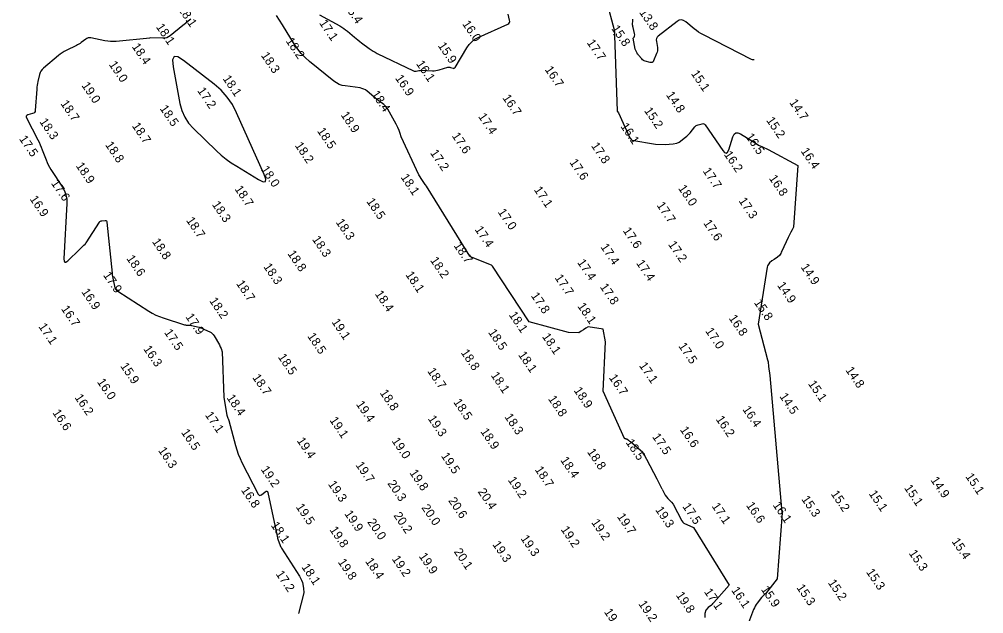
# Model space of a CAD drawing. Extents: x 824616 to 827440, y 158441 to 163197.
# Drawn here: x 826350 to 826901, y 160229 to 160569 of the extents above; entities that cross this region are included whole.
import ezdxf

# ---------------------------------------------------------------- set-up
doc = ezdxf.new("R2010")
doc.units = 0
for name, color, linetype in [('V-CHAN-CONT-EL14', 7, 'Continuous'), ('V-CHAN-CONT-EL16', 7, 'Continuous'), ('V-CHAN-CONT-EL18', 7, 'Continuous'), ('V-TOPO-SOUN', 7, 'Continuous')]:
    doc.layers.add(name, color=color, linetype=linetype)

msp = doc.modelspace()

# ---------------------------------------------------------------- linework, layer by layer
at = {"layer": 'V-CHAN-CONT-EL14'}
msp.add_lwpolyline([(826769.47, 160545.78), (826769.11, 160545.65), (826768.48, 160545.66), (826767.82, 160545.89), (826740.39, 160559.99), (826739.01, 160560.75), (826737.67, 160561.58), (826736.39, 160562.48), (826735.14, 160563.46), (826730.28, 160567.49), (826729.06, 160568.25), (826727.83, 160568.52), (826726.59, 160568.28), (826725.35, 160567.56), (826714.63, 160559.17), (826714.03, 160558.57), (826713.64, 160557.88), (826713.46, 160557.12), (826713.5, 160556.26), (826714.1, 160552.69), (826714.18, 160551.81), (826714.14, 160550.94), (826713.98, 160550.08), (826713.68, 160549.24), (826711.92, 160545.14), (826711.6, 160544.6), (826711.17, 160544.27), (826710.65, 160544.14), (826710.03, 160544.21), (826707.2, 160544.94), (826706.62, 160545.14), (826706.1, 160545.41), (826705.62, 160545.76), (826705.19, 160546.19), (826703.35, 160548.33), (826703.07, 160548.68), (826702.81, 160549.04), (826702.59, 160549.43), (826702.38, 160549.83), (826701.48, 160551.79), (826700.33, 160558.15), (826700.8, 160558.7), (826701.08, 160559.31), (826701.17, 160559.97), (826701.07, 160560.68), (826700.17, 160564.19), (826700.06, 160564.66), (826699.99, 160565.13), (826699.96, 160565.62), (826699.96, 160566.1), (826700.03, 160568.04), (826700.05, 160568.53), (826700.06, 160569.02)], dxfattribs=at)
at = {"layer": 'V-CHAN-CONT-EL16'}
for points in [[(826685.09, 160579.19), (826689.32, 160562.78), (826689.58, 160561.15), (826689.58, 160559.59), (826689.22, 160560.38)], [(826521.11, 160571.49), (826532.72, 160565.08), (826533.85, 160564.42), (826534.94, 160563.7), (826535.99, 160562.93), (826537.01, 160562.11), (826541.01, 160558.72), (826542.02, 160557.88), (826543.04, 160557.05), (826544.07, 160556.24), (826545.11, 160555.44), (826549.44, 160552.18), (826550.52, 160551.4), (826551.65, 160550.68), (826552.81, 160550.02), (826554, 160549.41), (826574.83, 160539.47), (826575.2, 160539.33), (826575.57, 160539.25), (826575.95, 160539.23), (826576.33, 160539.28), (826577.9, 160539.6), (826578.29, 160539.66), (826578.68, 160539.71), (826579.08, 160539.73), (826579.48, 160539.72), (826585.55, 160539.49), (826586.53, 160539.49), (826587.5, 160539.57), (826588.46, 160539.74), (826589.41, 160539.98), (826594.3, 160541.44), (826594.69, 160541.52), (826595.07, 160541.55), (826595.46, 160541.51), (826595.85, 160541.41), (826597.39, 160540.9), (826597.75, 160540.83), (826598.07, 160540.88), (826598.34, 160541.05), (826598.57, 160541.34), (826605.23, 160552.61), (826606.53, 160554.47), (826608.06, 160556.08), (826609.82, 160557.43), (826611.81, 160558.51), (826628.57, 160566.1), (826629.22, 160566.51), (826629.62, 160567.04), (826629.79, 160567.69), (826629.7, 160568.45), (826628.87, 160571.75)], [(826689.58, 160559.59), (826691.18, 160516.44), (826691.83, 160515.44), (826698.23, 160501.57), (826698.34, 160501.36), (826698.46, 160501.15), (826698.6, 160500.96), (826698.75, 160500.77), (826699.38, 160500.04), (826699.49, 160499.86), (826713.05, 160497.62), (826718.59, 160497.32)], [(826718.59, 160497.32), (826723.03, 160497.75), (826725.26, 160498.12), (826726.55, 160498.72), (826730.25, 160501.49), (826730.92, 160502.1), (826731.56, 160502.74), (826732.17, 160503.41), (826732.76, 160504.1), (826735.45, 160507.45), (826735.84, 160507.87), (826736.28, 160508.2), (826736.77, 160508.46), (826737.32, 160508.64), (826739.59, 160509.19), (826740.13, 160509.25), (826740.61, 160509.15), (826741.03, 160508.9), (826741.39, 160508.5), (826751.48, 160493.86), (826752.52, 160492.7), (826753.42, 160492.4), (826754.19, 160492.95), (826754.84, 160494.36), (826757.17, 160501.72), (826757.89, 160503.2), (826758.87, 160503.98), (826760.12, 160504.04), (826761.63, 160503.39), (826770.59, 160497.94), (826771.85, 160496.91), (826774.13, 160496.07), (826777.4, 160494.54)], [(826777.4, 160494.54), (826794.3, 160485.28)], [(826794.3, 160485.28), (826791.93, 160450.15), (826791.14, 160448.68), (826790.37, 160447.2), (826789.62, 160445.72), (826788.89, 160444.22), (826785.2, 160436.46), (826784.85, 160435.93), (826784.61, 160435.06), (826783.87, 160434.01), (826782.72, 160433.04), (826780.88, 160431.73), (826779.4, 160430.88), (826778.09, 160429.83), (826777.02, 160428.05), (826776.84, 160427.24), (826771.59, 160394.75)], [(826771.59, 160394.75), (826777.07, 160374.37), (826777.39, 160373.24), (826777.36, 160372.41), (826777.51, 160371.31), (826777.66, 160370.55), (826778.34, 160365.47)], [(826778.34, 160365.47), (826785.24, 160287.2), (826785.3, 160287)], [(826785.3, 160287), (826782.56, 160249.31), (826775.83, 160240.72), (826775.03, 160240.11), (826774.29, 160239.42), (826773.63, 160238.64), (826771.1, 160235.38), (826770.5, 160234.55), (826769.97, 160233.68), (826769.5, 160232.77), (826769.1, 160231.82), (826766.18, 160224.2)]]:
    msp.add_lwpolyline(points, dxfattribs=at)
at = {"layer": 'V-CHAN-CONT-EL18'}
for points in [[(826447.48, 160569.01), (826446, 160567.75), (826444.51, 160566.5), (826443, 160565.27), (826435.82, 160559.46), (826434.84, 160558.8), (826433.79, 160558.34), (826432.68, 160558.07), (826431.51, 160558.01), (826424.26, 160558.21), (826424.25, 160558.21), (826424.24, 160558.21), (826424.22, 160558.2), (826424.21, 160558.19), (826424.16, 160558.15), (826424.15, 160558.14), (826424.13, 160558.14), (826424.12, 160558.13), (826424.11, 160558.13), (826404.99, 160556.26), (826403.36, 160556.17), (826401.73, 160556.19), (826400.11, 160556.33), (826398.5, 160556.6), (826390.46, 160558.25), (826389.68, 160558.33), (826388.93, 160558.24), (826388.22, 160557.99), (826387.55, 160557.58), (826384.95, 160555.58), (826384.29, 160555.1), (826383.61, 160554.65), (826382.9, 160554.24), (826382.18, 160553.87), (826376.39, 160551.08), (826375.2, 160550.46), (826374.06, 160549.77), (826372.96, 160549.01), (826371.92, 160548.17), (826363.3, 160540.87), (826362.56, 160540.14), (826361.96, 160539.32), (826361.5, 160538.41), (826361.19, 160537.41), (826360.22, 160533.25), (826360, 160532.2), (826359.82, 160531.16), (826359.68, 160530.1), (826359.58, 160529.04), (826358.68, 160516.8), (826358.55, 160516.15), (826358.26, 160515.64), (826357.81, 160515.25), (826357.2, 160514.99), (826354.45, 160514.22), (826353.89, 160513.97), (826353.58, 160513.61), (826353.53, 160513.14), (826353.73, 160512.56), (826360.18, 160499.99), (826360.86, 160498.6), (826361.51, 160497.19), (826362.11, 160495.77), (826362.67, 160494.32), (826364.83, 160488.5), (826365.41, 160487.07), (826366.06, 160485.67), (826366.8, 160484.32), (826367.61, 160483), (826374.21, 160472.97), (826375.4, 160470.81), (826376.22, 160468.55), (826376.66, 160466.19), (826376.71, 160463.72), (826375.04, 160431.99), (826375.11, 160430.7), (826375.5, 160430.1), (826376.21, 160430.19), (826377.23, 160430.97), (826383.89, 160437.28), (826384.11, 160437.49), (826384.33, 160437.71), (826384.56, 160437.92), (826384.78, 160438.13), (826385.76, 160439.08), (826385.93, 160439.25), (826386.1, 160439.42), (826386.28, 160439.58), (826386.45, 160439.75), (826387.15, 160440.43), (826387.31, 160440.6), (826387.47, 160440.78), (826387.62, 160440.97), (826387.76, 160441.17), (826395.35, 160452.99), (826395.63, 160453.33), (826395.96, 160453.58), (826396.34, 160453.75), (826396.78, 160453.82), (826398.63, 160453.92), (826399.04, 160453.89), (826399.34, 160453.73), (826399.55, 160453.45), (826399.64, 160453.05), (826402.6, 160423.77), (826402.71, 160422.84), (826402.83, 160421.91), (826402.98, 160420.99), (826403.15, 160420.08), (826403.88, 160416.41), (826404.13, 160415.55), (826404.54, 160414.79), (826405.1, 160414.13), (826405.81, 160413.57), (826423.62, 160402.11), (826425.55, 160400.96), (826427.53, 160399.94), (826429.58, 160399.05), (826431.7, 160398.3), (826443.92, 160394.4), (826444.25, 160394.31), (826444.57, 160394.25), (826444.9, 160394.21), (826445.24, 160394.2), (826446.58, 160394.21), (826446.92, 160394.2), (826447.25, 160394.17), (826447.58, 160394.12), (826447.91, 160394.05), (826452.31, 160392.91), (826453.11, 160392.68), (826453.9, 160392.41), (826454.68, 160392.1), (826455.44, 160391.76), (826458.44, 160390.29), (826459.16, 160389.89), (826459.79, 160389.39), (826460.34, 160388.8), (826460.81, 160388.13), (826463.98, 160382.85), (826464.41, 160381.78), (826464.89, 160380.77), (826465.38, 160378.97), (826466.36, 160352.93)], [(826581.62, 160474.36), (826581.51, 160474.56), (826580, 160476.74), (826577.82, 160480.09), (826567.64, 160501.66), (826567.14, 160503.54), (826566.52, 160505.37), (826565.77, 160507.15), (826564.88, 160508.88), (826560.06, 160517.56), (826559.6, 160518.31), (826559.06, 160519), (826558.45, 160519.63), (826557.77, 160520.19), (826554.91, 160522.34), (826554.2, 160522.89), (826553.5, 160523.44), (826552.81, 160524), (826552.12, 160524.58), (826548.26, 160527.86), (826547.35, 160528.53), (826546.38, 160529.05), (826545.35, 160529.42), (826544.25, 160529.64), (826535.7, 160530.78), (826533.95, 160531.13), (826532.29, 160531.71), (826530.73, 160532.52), (826529.27, 160533.55), (826515.31, 160544.83), (826512.88, 160546.97), (826510.65, 160549.3), (826508.62, 160551.8), (826506.81, 160554.49), (826499.89, 160565.69), (826498.18, 160568.41), (826496.41, 160571.09)], [(826716.81, 160300.55), (826714.06, 160306.1), (826708, 160317.34), (826707, 160319.57), (826706.8, 160320.45), (826705.88, 160321.46), (826698.69, 160327.55), (826698.45, 160327.75), (826698.19, 160327.94), (826697.93, 160328.12), (826697.66, 160328.29), (826696.58, 160328.97), (826696.3, 160329.11), (826696.01, 160329.23), (826695.71, 160329.3), (826695.4, 160329.34), (826683.04, 160356.41), (826684.46, 160384.58), (826683.05, 160391.92), (826674.47, 160393.17), (826673.14, 160392.34), (826671.81, 160391.5), (826670.5, 160390.64), (826669.19, 160389.77), (826663.37, 160390.04), (826640.78, 160396.06), (826640.81, 160396.1), (826640.76, 160396.09), (826619.97, 160427.81), (826619.27, 160428.51), (826607.43, 160433.19), (826607.03, 160433.64), (826582.14, 160473.55), (826581.62, 160474.36)], [(826466.36, 160352.93), (826467.86, 160343.77), (826468.16, 160342.7), (826468.32, 160342.1), (826468.49, 160341.52), (826468.68, 160341.06), (826468.87, 160340.65), (826469, 160340.39), (826469.15, 160340.13), (826469.26, 160339.97), (826469.35, 160339.76), (826473.11, 160325.32), (826473.82, 160322.84), (826474.67, 160320.42), (826475.66, 160318.06), (826476.77, 160315.74), (826486.12, 160297.64), (826486.47, 160297.14), (826486.88, 160296.91), (826487.35, 160296.95), (826487.88, 160297.25), (826490.11, 160299), (826490.61, 160299.3), (826491.01, 160299.31), (826491.32, 160299.05), (826491.52, 160298.5), (826496.87, 160273.61), (826497.01, 160273.01), (826497.17, 160272.42), (826497.34, 160271.83), (826497.54, 160271.24), (826498.35, 160268.91), (826498.57, 160268.34), (826498.82, 160267.78), (826499.1, 160267.24), (826499.42, 160266.71), (826509.67, 160250.71), (826510.79, 160248.48), (826511.29, 160247.09), (826511.86, 160243.83), (826512.16, 160241.28), (826509.05, 160229.36)], [(826716.81, 160300.55), (826718.58, 160297.11), (826720.01, 160295.2), (826721.24, 160293.98), (826722.25, 160293.1), (826723.06, 160291.9), (826728.01, 160282.35), (826728.55, 160281.57), (826729.22, 160281.02), (826734.76, 160278.52), (826755.12, 160245.7), (826744.96, 160234.12), (826743.06, 160232.91), (826741.81, 160231.35), (826741.21, 160229.44), (826741.25, 160227.19)]]:
    msp.add_lwpolyline(points, dxfattribs=at)
msp.add_lwpolyline([(826444.08, 160512.96), (826446.29, 160509.54), (826449.08, 160506.42), (826462.25, 160493.73), (826464.94, 160491.28), (826467.76, 160488.99), (826470.7, 160486.85), (826473.76, 160484.88), (826486.26, 160477.32), (826488.81, 160476.08), (826490.2, 160476.15), (826490.44, 160477.53), (826489.52, 160480.21), (826473.73, 160515.45), (826471.29, 160520.13), (826468.33, 160524.41), (826464.87, 160528.3), (826460.91, 160531.79), (826443.43, 160545.39), (826440.11, 160547.45), (826438, 160547.53), (826437.1, 160545.62), (826437.41, 160541.72), (826441.36, 160520.73), (826442.43, 160516.69)], close=True, dxfattribs=at)

# ---------------------------------------------------------------- texts
at = {"layer": 'V-TOPO-SOUN'}
for s, p in [('18.1 ', (826440.07, 160574.68)), ('15.4 ', (826534.79, 160576.58)), ('13.8 ', (826703.54, 160572.83)), ('17.1 ', (826520.7, 160566.74)), ('16.0 ', (826602.41, 160566.24)), ('18.1 ', (826427.47, 160564.49)), ('15.8 ', (826687.62, 160563.58)), ('18.2 ', (826501.61, 160556.45)), ('17.7 ', (826673.6, 160555.49)), ('18.4 ', (826413.68, 160553.26)), ('15.9 ', (826588.48, 160553.85)), ('18.3 ', (826487.44, 160548.24)), ('19.0 ', (826400.54, 160543.07)), ('16.1 ', (826576.09, 160543.42)), ('16.7 ', (826649.58, 160540.2)), ('18.1 ', (826465.59, 160535)), ('16.9 ', (826564.08, 160535.25)), ('15.1 ', (826733.12, 160537.86)), ('19.0 ', (826384.94, 160531.08)), ('17.2 ', (826451.06, 160528.07)), ('18.4 ', (826550.5, 160526.18)), ('16.7 ', (826625.41, 160523.99)), ('14.8 ', (826718.86, 160525.66)), ('18.7 ', (826372.9, 160520.73)), ('18.5 ', (826429.62, 160517.92)), ('15.2 ', (826706.35, 160516.66)), ('14.7 ', (826789.3, 160521.33)), ('18.9 ', (826533.02, 160514.22)), ('17.4 ', (826611.51, 160513.36)), ('15.2 ', (826776.12, 160511.14)), ('18.3 ', (826360.88, 160510.4)), ('18.7 ', (826413.74, 160507.97)), ('18.5 ', (826519.52, 160505.05)), ('16.1 ', (826692.81, 160507.7)), ('17.5 ', (826349.28, 160500.56)), ('17.6 ', (826596.48, 160502.29)), ('16.5 ', (826764.29, 160501.82)), ('18.8 ', (826398.44, 160497.12)), ('18.2 ', (826506.79, 160496.8)), ('17.8 ', (826676.04, 160496.64)), ('17.2 ', (826584.08, 160492.49)), ('16.2 ', (826751.94, 160491.67)), ('16.4 ', (826795.81, 160493.57)), ('18.9 ', (826381.68, 160485.2)), ('18.0 ', (826487.33, 160483.18)), ('17.6 ', (826663.71, 160487.16)), ('18.1 ', (826567.25, 160478.62)), ('17.7 ', (826739.81, 160482.22)), ('16.8 ', (826777.62, 160478.05)), ('17.6 ', (826367.51, 160475.23)), ('18.0 ', (826725.78, 160472.36)), ('18.7 ', (826472.37, 160471.96)), ('17.1 ', (826643.36, 160471.5)), ('16.9 ', (826355.32, 160466.23)), ('18.3 ', (826459.45, 160463.08)), ('18.5 ', (826547.69, 160464.81)), ('17.7 ', (826713.49, 160462.65)), ('17.3 ', (826760.33, 160465.14)), ('17.0 ', (826622.71, 160458.77)), ('18.7 ', (826444.7, 160454)), ('18.3 ', (826530.18, 160452.96)), ('17.6 ', (826740.15, 160452.48)), ('17.4 ', (826609.57, 160448.82)), ('17.6 ', (826694.17, 160448.12)), ('18.8 ', (826425.21, 160441.84)), ('18.3 ', (826516.65, 160443.19)), ('18.7 ', (826597.54, 160439.62)), ('17.2 ', (826720.06, 160440.29)), ('18.8 ', (826502.61, 160434.95)), ('17.4 ', (826681.4, 160438.84)), ('18.6 ', (826410.55, 160432.25)), ('18.2 ', (826584.08, 160431.19)), ('17.4 ', (826668.13, 160429.94)), ('17.4 ', (826701.78, 160429.57)), ('17.9 ', (826397.27, 160422.71)), ('18.3 ', (826488.83, 160427.58)), ('18.1 ', (826570.01, 160422.95)), ('14.9 ', (826795.78, 160427.36)), ('18.7 ', (826473.25, 160417.89)), ('17.7 ', (826655.25, 160421.24)), ('14.9 ', (826782.33, 160416.9)), ('16.9 ', (826384.86, 160413.16)), ('18.4 ', (826552.53, 160412)), ('17.8 ', (826681.06, 160416.03)), ('18.2 ', (826457.93, 160408.04)), ('17.8 ', (826641.66, 160410.97)), ('15.8 ', (826769.1, 160407.01)), ('16.7 ', (826373.24, 160403.46)), ('18.1 ', (826668.24, 160405.01)), ('17.9 ', (826444.32, 160398.93)), ('19.1 ', (826527.8, 160395.98)), ('18.1 ', (826629.06, 160399.99)), ('16.8 ', (826754.67, 160398.14)), ('17.1 ', (826360.31, 160393.35)), ('17.5 ', (826432.13, 160389.98)), ('18.5 ', (826617.24, 160390.03)), ('17.0 ', (826741.29, 160390.76)), ('18.5 ', (826513.93, 160387.84)), ('18.1 ', (826648.01, 160387.65)), ('16.3 ', (826420.24, 160380.59)), ('18.8 ', (826601.6, 160378.47)), ('17.5 ', (826725.9, 160382.24)), ('18.5 ', (826497.14, 160375.93)), ('18.1 ', (826634.38, 160377.23)), ('15.9 ', (826407.09, 160370.77)), ('18.7 ', (826582.48, 160367.85)), ('17.1 ', (826703.43, 160371.08)), ('14.8 ', (826821.38, 160368.46)), ('18.7 ', (826482.5, 160364.27)), ('18.1 ', (826618.74, 160365.51)), ('16.7 ', (826686.19, 160364.19)), ('16.0 ', (826393.79, 160361.73)), ('18.9 ', (826666.12, 160356.87)), ('15.1 ', (826800.01, 160360.65)), ('16.2 ', (826380.99, 160352.83)), ('18.4 ', (826467.83, 160352.63)), ('18.8 ', (826555.33, 160355.47)), ('18.8 ', (826651.46, 160352.03)), ('14.5 ', (826783.64, 160353.45)), ('19.4 ', (826541.73, 160348.97)), ('18.5 ', (826597.34, 160350.17)), ('16.4 ', (826762.49, 160346.06)), ('16.6 ', (826368.32, 160344.11)), ('17.1 ', (826455.47, 160342.83)), ('19.1 ', (826526.65, 160339.84)), ('19.3 ', (826582.78, 160340.71)), ('18.3 ', (826626.56, 160341.79)), ('16.2 ', (826747.27, 160340.44)), ('16.6 ', (826726.81, 160334.41)), ('16.5 ', (826441.83, 160332.87)), ('18.9 ', (826612.81, 160333.37)), ('17.5 ', (826710.94, 160330.4)), ('19.4 ', (826507.93, 160328.14)), ('19.0 ', (826562.12, 160328)), ('18.5 ', (826695.83, 160327.15)), ('16.3 ', (826428.7, 160322.58)), ('19.5 ', (826590.3, 160319.44)), ('18.8 ', (826673.75, 160321.73)), ('19.7 ', (826541.51, 160314.24)), ('18.4 ', (826658.45, 160317.03)), ('19.2 ', (826487.34, 160311.74)), ('19.8 ', (826572.31, 160309.78)), ('18.7 ', (826643.88, 160311.63)), ('15.1 ', (826889.89, 160307.66)), ('19.3 ', (826525.77, 160303.32)), ('20.3 ', (826559.72, 160303.7)), ('19.2 ', (826628.51, 160305.62)), ('14.9 ', (826870, 160305.64)), ('16.8 ', (826476.03, 160299.98)), ('20.4 ', (826611.31, 160299.02)), ('15.2 ', (826813, 160297.76)), ('15.1 ', (826834.67, 160297.9)), ('15.1 ', (826854.89, 160301.12)), ('19.5 ', (826507.36, 160290.3)), ('20.0 ', (826579.14, 160289.9)), ('20.6 ', (826594.46, 160293.91)), ('17.5 ', (826728.19, 160290.57)), ('17.1 ', (826744.93, 160290.79)), ('16.6 ', (826764.59, 160291.23)), ('16.1 ', (826779.86, 160291.36)), ('15.3 ', (826796.19, 160294.76)), ('19.9 ', (826535.08, 160286.45)), ('20.2 ', (826563.16, 160285.41)), ('19.7 ', (826690.84, 160284.78)), ('19.3 ', (826712.7, 160288.65)), ('18.1 ', (826493.06, 160279.86)), ('20.0 ', (826548.18, 160281.7)), ('19.2 ', (826676.16, 160281.47)), ('19.8 ', (826526.63, 160277.27)), ('19.2 ', (826658.74, 160277.41)), ('19.3 ', (826619.65, 160268.91)), ('19.3 ', (826635.78, 160272.29)), ('15.4 ', (826882.02, 160270.6)), ('20.1 ', (826597.66, 160264.74)), ('15.3 ', (826857.53, 160263.9)), ('19.8 ', (826531.38, 160258.79)), ('18.4 ', (826546.98, 160259.25)), ('19.2 ', (826562.21, 160260.61)), ('19.9 ', (826577.63, 160262.16)), ('17.2 ', (826495.9, 160252)), ('18.1 ', (826510.59, 160255.97)), ('15.3 ', (826833.17, 160253.11)), ('15.2 ', (826811.33, 160247)), ('17.1 ', (826740.59, 160241.83)), ('16.1 ', (826756.1, 160242.74)), ('15.9 ', (826773.11, 160243.2)), ('15.3 ', (826793.38, 160244.2)), ('19.8 ', (826724.49, 160239.87)), ('19.2 ', (826683.43, 160230.34)), ('19.2 ', (826703.06, 160234.93))]:
    msp.add_text(s, height=5, rotation=304.2, dxfattribs=at).set_placement(p)

doc.saveas('drawing.dxf')
